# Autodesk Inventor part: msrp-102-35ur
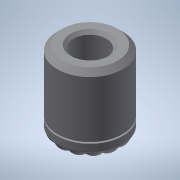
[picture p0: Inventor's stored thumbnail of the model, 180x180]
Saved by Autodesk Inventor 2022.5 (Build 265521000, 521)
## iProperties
Created: 2017-08
Part Number: msrp-102-35ur
Material: 一般
Document SubType Name: Modeling
Designer: imaocorp
Density: 1 g/cm^3
Appearance: 既定
Author: imaocorp
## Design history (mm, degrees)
node "msrp-102-35ur.x_t1"
node "msrp-102-35ur"
node "Base1"
